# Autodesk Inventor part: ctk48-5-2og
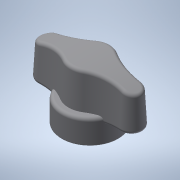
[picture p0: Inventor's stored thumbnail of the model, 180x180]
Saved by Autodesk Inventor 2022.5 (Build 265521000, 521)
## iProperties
Created: 2016-12
Part Number: ctk48-5-2og
Material: 一般
Document SubType Name: Modeling
Designer: imaocorp
Density: 1 g/cm^3
Appearance: 既定
Author: imaocorp
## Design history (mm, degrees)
node "ctk48-5-2og.x_t1"
node "ctk48-5-2og"
node "Base1"
